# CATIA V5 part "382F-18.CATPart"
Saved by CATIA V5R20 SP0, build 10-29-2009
Part number: 382F-18
Definition: NONE
Nomenclature: 382F-18
Source: Unknown
Description: 382F-18
Bounding box of the stored display mesh (mm): x -5 to 16, y -9 to 9, z -9 to 9
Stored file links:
  C:\Users\Utente\Desktop\IO LAVORO\3D X SITO CF\X SITO\PLASTICA\382F\382F-18.CATPart
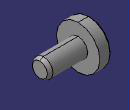
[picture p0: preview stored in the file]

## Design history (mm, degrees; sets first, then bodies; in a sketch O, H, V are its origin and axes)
Body1 "382F-18" (main body)
  Solid1: solid without history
